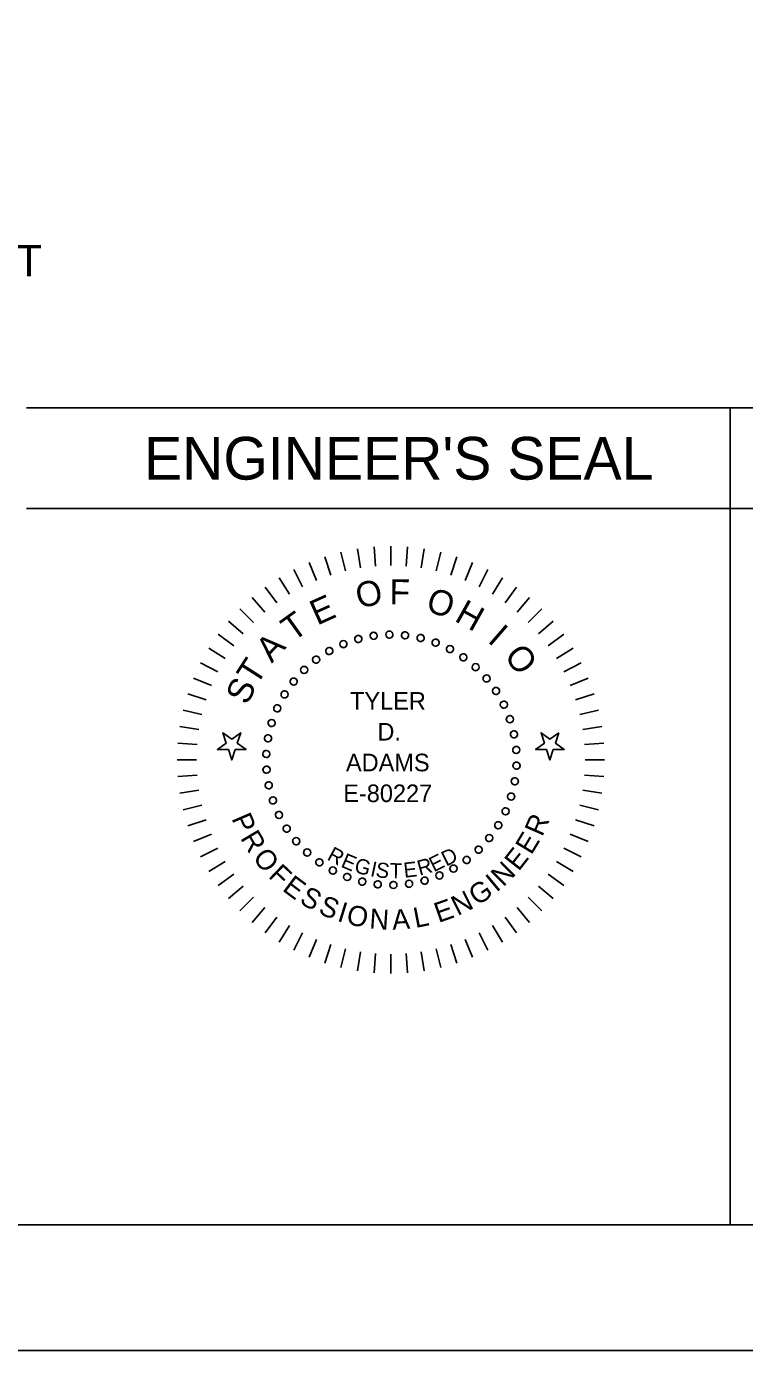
# Model space of a CAD drawing. Extents: x -7.1 to 34, y 0 to 22.
# Drawn here: x 23.6 to 26.46, y 0 to 5.27 of the extents above; entities that cross this region are included whole.
import ezdxf

# ---------------------------------------------------------------- set-up
doc = ezdxf.new("R2010")
doc.units = 0
for name, color, linetype in [('Default', 7, 'Continuous'), ('SH_Border', 7, 'Continuous'), ('SH_Cut_Line', 7, 'Continuous'), ('SH_Data', 7, 'Continuous'), ('SH_Text', 7, 'Continuous')]:
    doc.layers.add(name, color=color, linetype=linetype)

msp = doc.modelspace()

# ---------------------------------------------------------------- linework, layer by layer
at = {"layer": 'Default'}
for points in [[(24.8694, 3.1016), (24.8514, 3.1765)], [(24.9289, 3.1134), (24.9168, 3.1895)], [(24.9892, 3.1206), (24.9831, 3.1974)], [(25.0498, 3.1229), (25.0498, 3.2)], [(25.1105, 3.1206), (25.1165, 3.1974)], [(25.1707, 3.1134), (25.1828, 3.1895)], [(25.2303, 3.1016), (25.2483, 3.1765)], [(24.754, 3.0641), (24.7245, 3.1353)], [(24.811, 3.0851), (24.7872, 3.1584)], [(25.2887, 3.0851), (25.3125, 3.1584)], [(25.3456, 3.0641), (25.3751, 3.1353)], [(24.646, 3.009), (24.6057, 3.0747)], [(24.6989, 3.0387), (24.6639, 3.1074)], [(25.4007, 3.0387), (25.4357, 3.1074)], [(25.4537, 3.009), (25.494, 3.0747)], [(24.5955, 2.9753), (24.5502, 3.0377)], [(25.5042, 2.9753), (25.5495, 3.0377)], [(24.5033, 2.8965), (24.4488, 2.951)], [(24.5478, 2.9377), (24.4978, 2.9963)], [(25.5518, 2.9377), (25.6019, 2.9963)], [(25.5964, 2.8965), (25.6509, 2.951)], [(24.4621, 2.852), (24.4035, 2.902)], [(25.6376, 2.852), (25.6962, 2.902)], [(24.4245, 2.8043), (24.3621, 2.8496)], [(25.6752, 2.8043), (25.7375, 2.8496)], [(24.3908, 2.7538), (24.3251, 2.7941)], [(25.7089, 2.7538), (25.7746, 2.7941)], [(24.3611, 2.7009), (24.2924, 2.7359)], [(25.7385, 2.7009), (25.8072, 2.7359)], [(24.3357, 2.6458), (24.2645, 2.6753)], [(25.7639, 2.6458), (25.8351, 2.6753)], [(24.3147, 2.5888), (24.2414, 2.6126)], [(25.7849, 2.5888), (25.8582, 2.6126)], [(24.2982, 2.5304), (24.2233, 2.5484)], [(25.8014, 2.5304), (25.8764, 2.5484)], [(24.2864, 2.4709), (24.2103, 2.4829)], [(25.8133, 2.4709), (25.8894, 2.4829)], [(24.3952, 2.4167), (24.36, 2.3911), (24.4036, 2.3911), (24.417, 2.3496), (24.4305, 2.3911), (24.4741, 2.3911), (24.4388, 2.4167), (24.4523, 2.4582), (24.417, 2.4325), (24.3818, 2.4582), (24.3952, 2.4167)], [(25.7179, 2.4582), (25.6826, 2.4325), (25.6473, 2.4582), (25.6608, 2.4167), (25.6255, 2.3911), (25.6691, 2.3911), (25.6826, 2.3496), (25.6961, 2.3911), (25.7397, 2.3911), (25.7044, 2.4167), (25.7179, 2.4582)], [(24.2792, 2.4106), (24.2024, 2.4167)], [(25.8204, 2.4106), (25.8972, 2.4167)], [(24.2769, 2.35), (24.1998, 2.35)], [(25.8228, 2.35), (25.8998, 2.35)], [(24.2792, 2.2893), (24.2024, 2.2833)], [(25.8204, 2.2893), (25.8972, 2.2833)], [(24.2864, 2.2291), (24.2103, 2.217)], [(25.8894, 2.217), (25.8133, 2.2291)], [(24.2233, 2.1515), (24.2982, 2.1695)], [(25.8014, 2.1695), (25.8764, 2.1515)], [(24.3147, 2.1111), (24.2414, 2.0873)], [(25.7849, 2.1111), (25.8582, 2.0873)], [(24.3357, 2.0542), (24.2645, 2.0247)], [(25.7639, 2.0542), (25.8351, 2.0247)], [(24.3611, 1.9991), (24.2924, 1.9641)], [(25.7385, 1.9991), (25.8072, 1.9641)], [(24.3908, 1.9461), (24.3251, 1.9058)], [(25.7089, 1.9461), (25.7746, 1.9058)], [(24.4245, 1.8956), (24.3621, 1.8503)], [(24.4621, 1.848), (24.4035, 1.7979)], [(25.6376, 1.848), (25.6962, 1.7979)], [(25.6752, 1.8956), (25.7375, 1.8503)], [(24.5033, 1.8034), (24.4488, 1.7489)], [(25.5964, 1.8034), (25.6509, 1.7489)], [(24.5478, 1.7622), (24.4978, 1.7036)], [(25.5518, 1.7622), (25.6019, 1.7036)], [(24.5955, 1.7246), (24.5502, 1.6623)], [(24.646, 1.6909), (24.6057, 1.6252)], [(25.4537, 1.6909), (25.494, 1.6252)], [(25.5042, 1.7246), (25.5495, 1.6623)], [(24.6989, 1.6613), (24.6639, 1.5926)], [(24.754, 1.6359), (24.7245, 1.5647)], [(25.3456, 1.6359), (25.3751, 1.5647)], [(25.4007, 1.6613), (25.4357, 1.5926)], [(24.811, 1.6149), (24.7872, 1.5416)], [(24.8694, 1.5984), (24.8514, 1.5234)], [(24.9289, 1.5865), (24.9168, 1.5104)], [(25.1707, 1.5865), (25.1828, 1.5104)], [(25.2303, 1.5984), (25.2483, 1.5234)], [(25.2887, 1.6149), (25.3125, 1.5416)], [(24.9892, 1.5794), (24.9831, 1.5026)], [(25.0498, 1.577), (25.0498, 1.5)], [(25.1105, 1.5794), (25.1165, 1.5026)]]:
    msp.add_lwpolyline(points, dxfattribs=at)
for points in [[(24.3818, 2.4582), (24.417, 2.4325), (24.4523, 2.4582), (24.4388, 2.4167), (24.4741, 2.3911), (24.4305, 2.3911), (24.417, 2.3496), (24.4036, 2.3911), (24.36, 2.3911), (24.3952, 2.4167)], [(25.7179, 2.4582), (25.6826, 2.4325), (25.6473, 2.4582), (25.6608, 2.4167), (25.6255, 2.3911), (25.6691, 2.3911), (25.6826, 2.3496), (25.6961, 2.3911), (25.7397, 2.3911), (25.7044, 2.4167)]]:
    msp.add_lwpolyline(points, close=True, dxfattribs=at)
for centre in [(24.9202, 2.8309), (24.9815, 2.8436), (25.0439, 2.8485), (25.1064, 2.8456), (25.1681, 2.8349), (24.8048, 2.783), (24.861, 2.8105), (25.2279, 2.8165), (25.2849, 2.7908), (24.7526, 2.7486), (25.3383, 2.7581), (24.705, 2.7079), (25.3872, 2.719), (25.4307, 2.6741), (24.6629, 2.6616), (25.4683, 2.6241), (24.6269, 2.6104), (25.4994, 2.5697), (24.5977, 2.5551), (24.5756, 2.4965), (25.5234, 2.5119), (24.561, 2.4357), (25.5399, 2.4516), (24.5542, 2.3734), (25.5488, 2.3896), (24.5552, 2.3109), (25.5498, 2.3271), (25.543, 2.2648), (24.5641, 2.2489), (25.5284, 2.204), (24.5806, 2.1886), (24.6046, 2.1308), (25.5063, 2.1454), (24.6356, 2.0764), (25.477, 2.0901), (24.6732, 2.0264), (25.399, 1.9926), (25.4411, 2.0389), (24.7168, 1.9815), (24.7657, 1.9424), (25.3514, 1.9519), (24.819, 1.9097), (24.8761, 1.884), (25.243, 1.89), (25.2991, 1.9175), (24.9359, 1.8656), (24.9976, 1.8549), (25.0601, 1.852), (25.1225, 1.8569), (25.1838, 1.8697)]:
    msp.add_circle(centre, 0.0141, dxfattribs=at)
for centre, radius, start, end in [((24.9202, 2.8309), 0.0141, 14.4, 194.4), ((24.9815, 2.8436), 0.0141, 7.2, 187.2), ((24.9815, 2.8436), 0.0141, 285.3271, 7.2), ((25.0439, 2.8485), 0.0141, 0, 180), ((25.0439, 2.8485), 0.0141, 180, 263.7371), ((25.0439, 2.8485), 0.0141, 278.1271, 360), ((25.1064, 2.8456), 0.0141, 172.8, 256.5371), ((25.1064, 2.8456), 0.0141, 352.8, 172.8), ((25.1681, 2.8349), 0.0141, 345.6, 165.6), ((24.8048, 2.783), 0.0141, 28.8, 208.8), ((24.861, 2.8105), 0.0141, 21.6, 201.6), ((24.861, 2.8105), 0.0141, 201.6, 285.3371), ((25.052, 2.3503), 0.4843, 112.3226, 112.7416), ((24.861, 2.8105), 0.0141, 299.7271, 21.6), ((24.9202, 2.8309), 0.0141, 194.4, 278.1371), ((25.052, 2.3503), 0.4843, 105.1226, 105.5416), ((24.9202, 2.8309), 0.0141, 292.5271, 14.4), ((24.9815, 2.8436), 0.0141, 187.2, 270.9371), ((25.052, 2.3503), 0.4843, 97.9226, 98.3416), ((25.052, 2.3503), 0.4843, 90.7226, 91.1416), ((25.052, 2.3503), 0.4843, 83.5226, 83.9416), ((25.1064, 2.8456), 0.0141, 270.9271, 352.8), ((25.1681, 2.8349), 0.0141, 165.6, 249.3371), ((25.052, 2.3503), 0.4843, 76.3226, 76.7416), ((25.1681, 2.8349), 0.0141, 263.7271, 345.6), ((25.2279, 2.8165), 0.0141, 158.4, 242.1371), ((25.2279, 2.8165), 0.0141, 338.4, 158.4), ((25.052, 2.3503), 0.4843, 69.1226, 69.5416), ((25.2279, 2.8165), 0.0141, 256.5271, 338.4), ((25.2849, 2.7908), 0.0141, 151.2, 234.9371), ((25.2849, 2.7908), 0.0141, 331.2, 151.2), ((24.7526, 2.7486), 0.0141, 36, 216), ((24.7526, 2.7486), 0.0141, 216, 299.7371), ((24.7526, 2.7486), 0.0141, 314.1271, 36), ((24.8048, 2.783), 0.0141, 208.8, 292.5371), ((25.052, 2.3503), 0.4843, 119.5226, 119.9416), ((24.8048, 2.783), 0.0141, 306.9271, 28.8), ((25.052, 2.3503), 0.4843, 61.9226, 62.3416), ((25.2849, 2.7908), 0.0141, 249.3271, 331.2), ((25.3383, 2.7581), 0.0141, 144, 227.7371), ((25.3383, 2.7581), 0.0141, 324, 144), ((25.052, 2.3503), 0.4843, 54.7226, 55.1416), ((25.3383, 2.7581), 0.0141, 242.1271, 324), ((24.705, 2.7079), 0.0141, 43.2, 223.2), ((24.705, 2.7079), 0.0141, 223.2, 306.9371), ((25.052, 2.3503), 0.4843, 133.9226, 134.3416), ((24.705, 2.7079), 0.0141, 321.3271, 43.2), ((25.052, 2.3503), 0.4843, 126.7226, 127.1416), ((25.3872, 2.719), 0.0141, 136.8, 220.5371), ((25.052, 2.3503), 0.4843, 47.5226, 47.9416), ((25.3872, 2.719), 0.0141, 316.8, 136.8), ((25.3872, 2.719), 0.0141, 234.9271, 316.8), ((25.4307, 2.6741), 0.0141, 309.6, 129.6), ((24.6629, 2.6616), 0.0141, 50.4, 230.4), ((24.6629, 2.6616), 0.0141, 230.4, 314.1371), ((24.6629, 2.6616), 0.0141, 328.5271, 50.4), ((25.052, 2.3503), 0.4843, 141.1226, 141.5416), ((25.4307, 2.6741), 0.0141, 129.6, 213.3371), ((25.052, 2.3503), 0.4843, 40.3226, 40.7416), ((25.4307, 2.6741), 0.0141, 227.7271, 309.6), ((25.4683, 2.6241), 0.0141, 122.4, 206.1371), ((25.4683, 2.6241), 0.0141, 302.4, 122.4), ((24.6269, 2.6104), 0.0141, 57.6, 237.6), ((24.6269, 2.6104), 0.0141, 237.6, 321.3371), ((24.6269, 2.6104), 0.0141, 335.7271, 57.6), ((25.052, 2.3503), 0.4843, 148.3226, 148.7416), ((25.052, 2.3503), 0.4843, 33.1226, 33.5416), ((25.4683, 2.6241), 0.0141, 220.5271, 302.4), ((25.4994, 2.5697), 0.0141, 115.2, 198.9371), ((25.4994, 2.5697), 0.0141, 295.2, 115.2), ((24.5977, 2.5551), 0.0141, 64.8, 244.8), ((24.5977, 2.5551), 0.0141, 244.8, 328.5371), ((24.5977, 2.5551), 0.0141, 342.9271, 64.8), ((25.052, 2.3503), 0.4843, 155.5226, 155.9416), ((25.052, 2.3503), 0.4843, 25.9226, 26.3416), ((25.4994, 2.5697), 0.0141, 213.3271, 295.2), ((24.5756, 2.4965), 0.0141, 72, 252), ((24.5756, 2.4965), 0.0141, 252, 335.7371), ((24.5756, 2.4965), 0.0141, 350.1271, 72), ((25.052, 2.3503), 0.4843, 162.7226, 163.1416), ((25.5234, 2.5119), 0.0141, 108, 191.7371), ((25.052, 2.3503), 0.4843, 18.7226, 19.1416), ((25.5234, 2.5119), 0.0141, 206.1271, 288), ((25.5234, 2.5119), 0.0141, 288, 108), ((24.561, 2.4357), 0.0141, 79.2, 259.2), ((24.561, 2.4357), 0.0141, 259.2, 342.9371), ((24.561, 2.4357), 0.0141, 357.3271, 79.2), ((25.052, 2.3503), 0.4843, 169.9226, 170.3416), ((25.5399, 2.4516), 0.0141, 100.8, 184.5371), ((25.052, 2.3503), 0.4843, 11.5226, 11.9416), ((25.5399, 2.4516), 0.0141, 198.9271, 280.8), ((25.5399, 2.4516), 0.0141, 280.8, 100.8), ((24.5542, 2.3734), 0.0141, 86.4, 266.4), ((24.5542, 2.3734), 0.0141, 266.4, 350.1371), ((24.5542, 2.3734), 0.0141, 4.5271, 86.4), ((25.052, 2.3503), 0.4843, 177.1226, 177.5416), ((25.5488, 2.3896), 0.0141, 93.6, 177.3371), ((25.052, 2.3503), 0.4843, 4.3226, 4.7416), ((25.5488, 2.3896), 0.0141, 191.7271, 273.6), ((25.5488, 2.3896), 0.0141, 273.6, 93.6), ((24.5552, 2.3109), 0.0141, 93.6, 273.6), ((24.5552, 2.3109), 0.0141, 11.7271, 93.6), ((25.052, 2.3503), 0.4843, 357.1226, 357.5416), ((25.5498, 2.3271), 0.0141, 184.5271, 266.4), ((25.5498, 2.3271), 0.0141, 86.4, 170.1371), ((25.5498, 2.3271), 0.0141, 266.4, 86.4), ((24.5552, 2.3109), 0.0141, 273.6, 357.3371), ((25.052, 2.3503), 0.4843, 184.3226, 184.7416), ((25.052, 2.3503), 0.4843, 349.9226, 350.3416), ((25.543, 2.2648), 0.0141, 177.3271, 259.2), ((25.543, 2.2648), 0.0141, 79.2, 162.9371), ((25.543, 2.2648), 0.0141, 259.2, 79.2), ((24.5641, 2.2489), 0.0141, 100.8, 280.8), ((24.5641, 2.2489), 0.0141, 18.9271, 100.8), ((24.5641, 2.2489), 0.0141, 280.8, 4.5371), ((25.052, 2.3503), 0.4843, 191.5226, 191.9416), ((25.5284, 2.204), 0.0141, 72, 155.7371), ((25.5284, 2.204), 0.0141, 252, 72), ((24.5806, 2.1886), 0.0141, 108, 288), ((24.5806, 2.1886), 0.0141, 26.1271, 108), ((24.5806, 2.1886), 0.0141, 288, 11.7371), ((25.052, 2.3503), 0.4843, 198.7226, 199.1416), ((25.5284, 2.204), 0.0141, 170.1271, 252), ((25.052, 2.3503), 0.4843, 342.7226, 343.1416), ((24.6046, 2.1308), 0.0141, 115.2, 295.2), ((24.6046, 2.1308), 0.0141, 33.3271, 115.2), ((24.6046, 2.1308), 0.0141, 295.2, 18.9371), ((25.052, 2.3503), 0.4843, 205.9226, 206.3416), ((25.5063, 2.1454), 0.0141, 162.9271, 244.8), ((25.052, 2.3503), 0.4843, 335.5226, 335.9416), ((25.5063, 2.1454), 0.0141, 64.8, 148.5371), ((25.5063, 2.1454), 0.0141, 244.8, 64.8), ((24.6356, 2.0764), 0.0141, 122.4, 302.4), ((24.6356, 2.0764), 0.0141, 40.5271, 122.4), ((24.6356, 2.0764), 0.0141, 302.4, 26.1371), ((25.052, 2.3503), 0.4843, 213.1226, 213.5416), ((25.477, 2.0901), 0.0141, 155.7271, 237.6), ((25.052, 2.3503), 0.4843, 328.3226, 328.7416), ((25.477, 2.0901), 0.0141, 57.6, 141.3371), ((25.477, 2.0901), 0.0141, 237.6, 57.6), ((24.6732, 2.0264), 0.0141, 129.6, 309.6), ((24.6732, 2.0264), 0.0141, 47.7271, 129.6), ((24.6732, 2.0264), 0.0141, 309.6, 33.3371), ((25.052, 2.3503), 0.4843, 220.3226, 220.7416), ((25.052, 2.3503), 0.4843, 313.9226, 314.3416), ((25.399, 1.9926), 0.0141, 223.2, 43.2), ((25.399, 1.9926), 0.0141, 43.2, 126.9371), ((25.4411, 2.0389), 0.0141, 148.5271, 230.4), ((25.052, 2.3503), 0.4843, 321.1226, 321.5416), ((25.4411, 2.0389), 0.0141, 50.4, 134.1371), ((25.4411, 2.0389), 0.0141, 230.4, 50.4), ((24.7168, 1.9815), 0.0141, 136.8, 316.8), ((24.7168, 1.9815), 0.0141, 54.9271, 136.8), ((25.052, 2.3503), 0.4843, 227.5226, 227.9416), ((24.7168, 1.9815), 0.0141, 316.8, 40.5371), ((24.7657, 1.9424), 0.0141, 144, 324), ((24.7657, 1.9424), 0.0141, 62.1271, 144), ((25.052, 2.3503), 0.4843, 234.7226, 235.1416), ((24.7657, 1.9424), 0.0141, 324, 47.7371), ((25.3514, 1.9519), 0.0141, 134.1271, 216), ((25.3514, 1.9519), 0.0141, 216, 36), ((25.052, 2.3503), 0.4843, 306.7226, 307.1416), ((25.3514, 1.9519), 0.0141, 36, 119.7371), ((25.399, 1.9926), 0.0141, 141.3271, 223.2), ((24.819, 1.9097), 0.0141, 151.2, 331.2), ((24.819, 1.9097), 0.0141, 69.3271, 151.2), ((25.052, 2.3503), 0.4843, 241.9226, 242.3416), ((24.819, 1.9097), 0.0141, 331.2, 54.9371), ((24.8761, 1.884), 0.0141, 76.5271, 158.4), ((25.052, 2.3503), 0.4843, 249.1226, 249.5416), ((24.8761, 1.884), 0.0141, 338.4, 62.1371), ((25.243, 1.89), 0.0141, 119.7271, 201.6), ((25.052, 2.3503), 0.4843, 292.3226, 292.7416), ((25.243, 1.89), 0.0141, 21.6, 105.3371), ((25.2991, 1.9175), 0.0141, 126.9271, 208.8), ((25.2991, 1.9175), 0.0141, 208.8, 28.8), ((25.052, 2.3503), 0.4843, 299.5226, 299.9416), ((25.2991, 1.9175), 0.0141, 28.8, 112.5371), ((24.8761, 1.884), 0.0141, 158.4, 338.4), ((24.9359, 1.8656), 0.0141, 165.6, 345.6), ((24.9359, 1.8656), 0.0141, 83.7271, 165.6), ((25.052, 2.3503), 0.4843, 256.3226, 256.7416), ((24.9359, 1.8656), 0.0141, 345.6, 69.3371), ((24.9976, 1.8549), 0.0141, 172.8, 352.8), ((24.9976, 1.8549), 0.0141, 90.9271, 172.8), ((25.052, 2.3503), 0.4843, 263.5226, 263.9416), ((24.9976, 1.8549), 0.0141, 352.8, 76.5371), ((25.0601, 1.852), 0.0141, 98.1271, 180), ((25.0601, 1.852), 0.0141, 180, 0), ((25.052, 2.3503), 0.4843, 270.7226, 271.1416), ((25.0601, 1.852), 0.0141, 360, 83.7371), ((25.1225, 1.8569), 0.0141, 105.3271, 187.2), ((25.1225, 1.8569), 0.0141, 187.2, 7.2), ((25.052, 2.3503), 0.4843, 277.9226, 278.3416), ((25.1225, 1.8569), 0.0141, 7.2, 90.9371), ((25.1838, 1.8697), 0.0141, 112.5271, 194.4), ((25.1838, 1.8697), 0.0141, 194.4, 14.4), ((25.052, 2.3503), 0.4843, 285.1226, 285.5416), ((25.1838, 1.8697), 0.0141, 14.4, 98.1371), ((25.243, 1.89), 0.0141, 201.6, 21.6)]:
    msp.add_arc(centre, radius, start, end, dxfattribs=at)
at = {"layer": 'SH_Border'}
msp.add_lwpolyline([(1.5, 21.5), (33.5, 21.5), (33.5, 0.5), (1.5, 0.5)], close=True, dxfattribs=at)
at = {"layer": 'SH_Cut_Line'}
msp.add_lwpolyline([(0, 0), (34, 0), (34, 22), (0, 22)], close=True, dxfattribs=at)
at = {"layer": 'SH_Data'}
for p, q in [((23.6, 3.75), (26.4, 3.75)), ((26.4, 0.5), (26.4, 3.75)), ((26.4, 3.75), (29.2, 3.75)), ((26.4, 3.75), (26.4, 0.5)), ((23.6, 3.35), (26.4, 3.35)), ((26.4, 3.35), (29.2, 3.35))]:
    msp.add_line(p, q, dxfattribs=at)

# ---------------------------------------------------------------- texts
at = {"layer": 'Default'}
for s, height, rotation, p in [('O', 0.1, 13.3854, (24.9231, 2.9511)), ('F', 0.1, 359.678, (25.0445, 2.9684)), ('E', 0.1, 24.2623, (24.7568, 2.8836)), ('O', 0.1, 342.0191, (25.1845, 2.9435)), ('H', 0.1, 330.9889, (25.2991, 2.9046)), ('T', 0.1, 35.6514, (24.6603, 2.8177)), ('I', 0.1, 319.1518, (25.4312, 2.8212)), ('A', 0.1, 46.5856, (24.5758, 2.7326)), ('O', 0.1, 307.5099, (25.4973, 2.762)), ('T', 0.1, 57.2766, (24.515, 2.6415)), ('S', 0.1, 64.8956, (24.4793, 2.5646)), ('P', 0.08, 293.3065, (24.4148, 2.117)), ('R', 0.08, 66.294, (25.652, 2.0415)), ('R', 0.08, 300.7913, (24.449, 2.0389)), ('E', 0.08, 58.867, (25.6087, 1.9689)), ('R', 0.06, 331.5179, (24.7922, 1.9549)), ('E', 0.08, 51.8972, (25.5583, 1.9039)), ('O', 0.08, 308.9294, (24.4971, 1.9594)), ('E', 0.06, 337.0101, (24.8474, 1.9257)), ('G', 0.06, 344.9102, (24.9007, 1.9038)), ('R', 0.06, 15.2924, (25.164, 1.889)), ('E', 0.06, 26.5869, (25.2208, 1.9022)), ('D', 0.06, 26.8755, (25.2702, 1.9251)), ('F', 0.08, 316.3676, (24.5591, 1.8847)), ('I', 0.06, 347.8825, (24.965, 1.8882)), ('S', 0.06, 351.4682, (24.9866, 1.885)), ('T', 0.06, 359.0333, (25.0452, 1.8794)), ('E', 0.06, 6.5708, (25.1037, 1.8808)), ('N', 0.08, 44.7866, (25.497, 1.8422)), ('E', 0.08, 323.0948, (24.6145, 1.8323)), ('G', 0.08, 34.2643, (25.3941, 1.7673)), ('I', 0.08, 39.7574, (25.4698, 1.8208)), ('S', 0.08, 330.2332, (24.6822, 1.7822)), ('S', 0.08, 337.5402, (24.7574, 1.7401)), ('E', 0.08, 19.438, (25.2394, 1.7007)), ('N', 0.08, 26.5487, (25.3156, 1.7278)), ('I', 0.08, 342.597, (24.833, 1.7102)), ('O', 0.08, 348.1963, (24.8691, 1.6978)), ('N', 0.08, 356.0181, (24.9627, 1.679)), ('A', 0.08, 3.7707, (25.057, 1.6736)), ('L', 0.08, 10.971, (25.1478, 1.681))]:
    msp.add_text(s, height=height, rotation=rotation, dxfattribs=at).set_placement(p)
for s, p in [('TYLER', (24.8875, 2.5495)), ('D.', (24.9963, 2.427)), ('ADAMS', (24.8712, 2.3045)), ('E-80227', (24.8604, 2.182))]:
    msp.add_text(s, height=0.07, dxfattribs=at).set_placement(p)
at = {"layer": 'SH_Data'}
msp.add_text("ENGINEER'S SEAL", height=0.17, dxfattribs=at).set_placement((24.0676, 3.465))
at = {"layer": 'SH_Text'}
msp.add_text('WATERWAY PERMIT', height=0.125, dxfattribs=at).set_placement((21.9991, 4.2735))

doc.saveas('drawing.dxf')
